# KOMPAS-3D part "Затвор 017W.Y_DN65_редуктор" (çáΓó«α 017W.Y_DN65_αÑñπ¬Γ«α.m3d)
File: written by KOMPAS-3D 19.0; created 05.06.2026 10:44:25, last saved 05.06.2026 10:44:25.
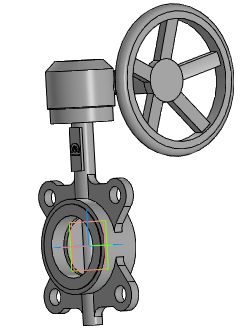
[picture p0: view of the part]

Document properties: Автор: Энергия; Полное имя файла: ..\..\..\3d для проектировщиков\x.x Тип 017W.Y(S) Затвор дисковый поворотный межфланцевый\Затвор 017W.Y(S)_DN50-DN1200_редуктор\Затвор 017W.Y_DN65_редуктор.a3d

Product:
- Part/product: Затвор 017W.Y_DN65_редуктор
    Масса: 5.78192

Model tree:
1. Операция без истории:1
